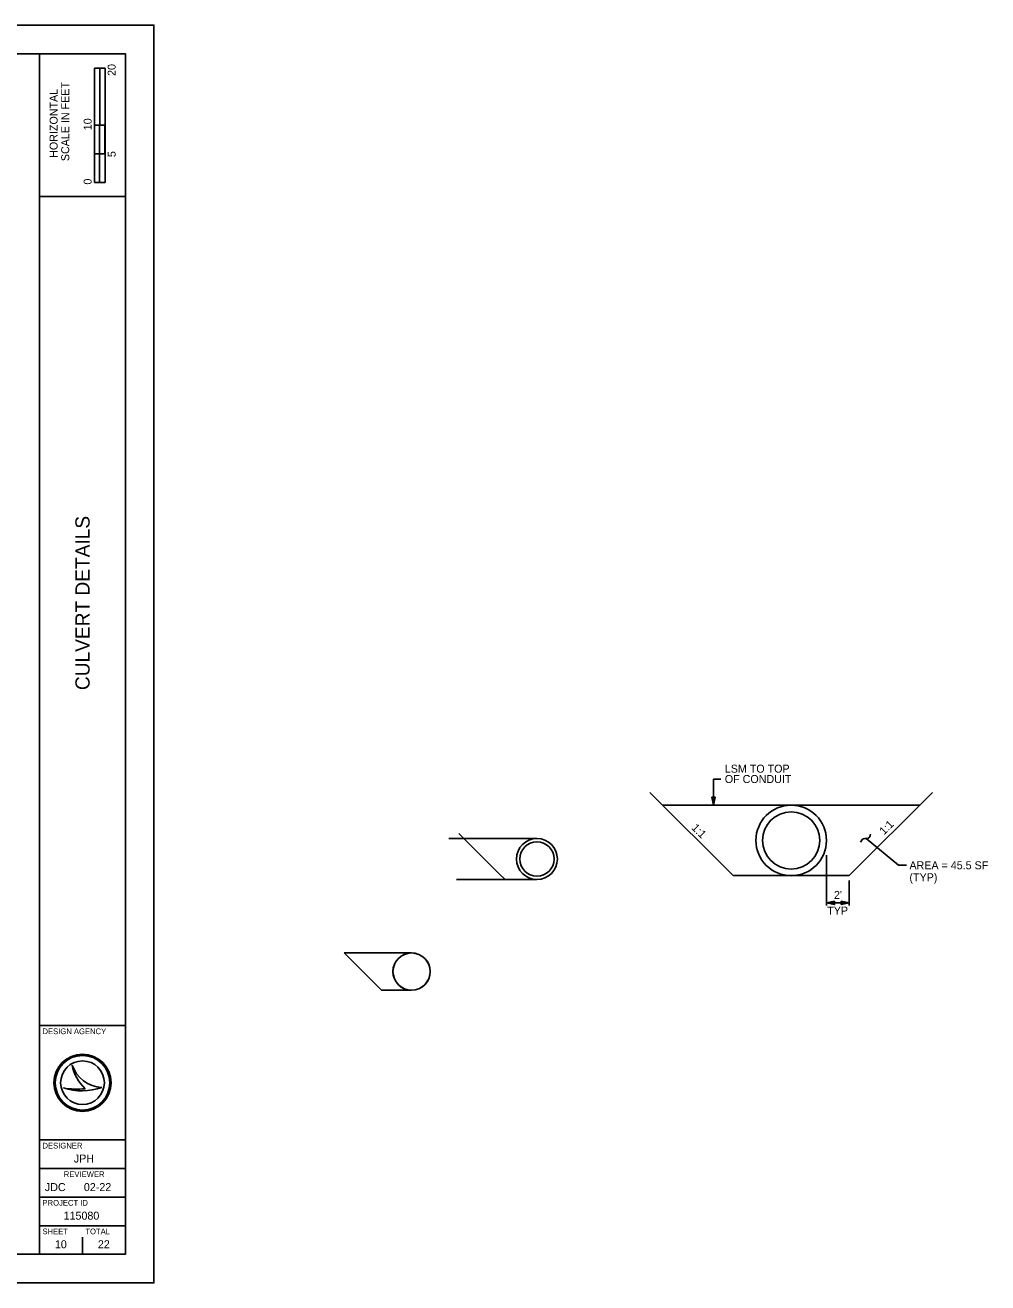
# Model space of a CAD drawing. Extents: x 0 to 486, y 0 to 220.
# Drawn here: x 317.5 to 485.8, y 0 to 220 of the extents above; entities that cross this region are included whole.
import ezdxf

# ---------------------------------------------------------------- set-up
doc = ezdxf.new("R2010")
doc.units = 0
for name, color, linetype in [('DR_P_Culvert', 7, 'Continuous'), ('DR_X_Culvert', 7, 'Continuous'), ('GE_X_Alignment', 7, 'Continuous'), ('GE_X_Alignment_100_Cardinal_Points', 7, 'Continuous'), ('MT_P_Temp_Road', 7, 'Continuous'), ('PF_X_Ground_Line', 7, 'Continuous'), ('XS_X_Pavt', 7, 'Continuous')]:
    doc.layers.add(name, color=color, linetype=linetype)

msp = doc.modelspace()

# ---------------------------------------------------------------- linework, layer by layer
at = {"layer": 'DR_P_Culvert'}
for p, q in [((406.97, 77.73), (391.55, 77.73)), ((406.97, 70.56), (392.92, 70.56)), ((385.05, 57.72), (373.26, 57.72)), ((379.79, 51.19), (373.26, 57.72)), ((385.05, 51.19), (379.79, 51.19))]:
    msp.add_line(p, q, dxfattribs=at)
msp.add_lwpolyline([(401.39, 70.56), (400.39, 71.56), (393.34, 78.61)], dxfattribs=at)
for centre, radius in [((406.97, 74.14), 3.58), ((406.97, 74.14), 3), ((385.05, 54.45), 3.26), ((385.05, 54.45), 3.25)]:
    msp.add_circle(centre, radius, dxfattribs=at)
at = {"layer": 'DR_X_Culvert'}
msp.add_lwpolyline([(0, 0), (340, 0), (340, 220), (0, 220)], close=True, dxfattribs=at)
at = {"layer": 'GE_X_Alignment'}
for points in [[(437.56, 84.96), (438.12, 84.96), (437.84, 83.56)], [(459, 66.74), (459, 66.18), (457.6, 66.46)], [(460.2, 66.18), (460.2, 66.74), (461.6, 66.46)]]:
    msp.add_lwpolyline(points, close=True, dxfattribs=at)
at = {"layer": 'GE_X_Alignment_100_Cardinal_Points'}
for p, q in [((437.84, 83.56), (437.84, 88.13)), ((437.84, 88.13), (439.14, 88.13)), ((464.54, 77.71), (470.21, 73.04)), ((457.6, 74.8), (457.6, 66.02)), ((470.21, 73.04), (471.58, 73.04)), ((461.6, 70.4), (461.6, 66.02)), ((457.6, 66.46), (461.6, 66.46))]:
    msp.add_line(p, q, dxfattribs=at)
msp.add_spline([(463.58, 77.07), (464.09, 77.68), (464.96, 77.77), (465.33, 78.5)], degree=3, dxfattribs=at)
at = {"layer": 'MT_P_Temp_Road'}
for p, q in [((441.27, 71.23), (426.72, 85.78)), ((461.6, 71.23), (476.16, 85.78)), ((473.94, 83.56), (428.94, 83.56)), ((441.27, 71.23), (451.44, 71.23)), ((451.44, 71.23), (461.6, 71.23))]:
    msp.add_line(p, q, dxfattribs=at)
for radius in [6.17, 5]:
    msp.add_circle((451.44, 77.39), radius, dxfattribs=at)
at = {"layer": 'PF_X_Ground_Line'}
for p, q in [((320, 5), (320, 215)), ((320, 190), (335, 190)), ((320, 45), (335, 45)), ((320, 25), (335, 25)), ((320, 20), (335, 20)), ((320, 15), (335, 15)), ((320, 10), (335, 10))]:
    msp.add_line(p, q, dxfattribs=at)
msp.add_lwpolyline([(15, 215), (335, 215), (335, 5), (15, 5)], close=True, dxfattribs=at)
at = {"layer": 'XS_X_Pavt'}
for p, q in [((329.57, 192.5), (329.57, 212.5)), ((331.44, 212.5), (329.57, 212.5)), ((329.57, 202.5), (329.57, 212.5)), ((329.57, 212.5), (330.5, 212.5)), ((330.5, 212.5), (330.51, 212.5)), ((330.51, 212.5), (330.51, 202.5)), ((331.44, 212.5), (331.44, 192.5)), ((330.51, 202.5), (329.57, 202.5)), ((331.43, 202.5), (330.5, 202.5)), ((330.5, 202.5), (330.5, 197.5)), ((331.43, 197.5), (331.43, 202.5)), ((330.5, 197.5), (329.57, 197.5)), ((329.57, 197.5), (329.57, 192.5)), ((330.5, 192.5), (330.5, 197.5)), ((330.5, 197.5), (331.43, 197.5)), ((331.44, 192.5), (329.57, 192.5)), ((329.57, 192.5), (330.5, 192.5)), ((325.67, 38.1), (325.67, 38.1)), ((324.17, 34.1), (324.17, 34.1)), ((327.5, 35), (327.5, 35)), ((330.87, 34.19), (330.87, 34.19)), ((323.75, 6.75), (323.75, 6.75)), ((327.5, 5), (327.5, 8))]:
    msp.add_line(p, q, dxfattribs=at)
for radius in [5, 4.77, 4.77, 3.82]:
    msp.add_circle((327.5, 35), radius, dxfattribs=at)
for centre, radius, start, end in [((331.16, 39.98), 5.8, 198.9257, 198.9319), ((333.47, 39.7), 7.96, 191.6379, 191.6421), ((331.16, 39.98), 5.8, 198.9319, 267.1657), ((333.47, 39.7), 7.96, 191.6421, 226.0947), ((327.39, 43.7), 10.13, 251.4576, 290.0832), ((326.48, 46.54), 12.66, 259.4964, 259.4995), ((327.39, 43.7), 10.13, 251.4527, 251.4576), ((326.48, 46.54), 12.66, 259.4995, 276.6672)]:
    msp.add_arc(centre, radius, start, end, dxfattribs=at)

# ---------------------------------------------------------------- texts
at = {"layer": 'GE_X_Alignment_100_Cardinal_Points'}
for s, p in [('LSM TO TOP', (439.83, 89.24)), ('OF CONDUIT', (439.83, 87.43)), ('AREA = 45.5 SF', (472.12, 72.34)), ('(TYP)', (472.12, 70.24)), ("2'", (458.92, 67.16)), ('TYP', (457.74, 64.41))]:
    msp.add_text(s, height=1.4, dxfattribs=at).set_placement(p)
for rotation, p in [(315, (433.92, 79.49)), (45, (467.68, 78.25))]:
    msp.add_text('1:1', height=1.4, rotation=rotation, dxfattribs=at).set_placement(p)
at = {"layer": 'XS_X_Pavt'}
for s, height, p in [('20', 1.4, (333.3, 211.12)), ('SCALE IN FEET', 1.4, (325.18, 196.21)), ('HORIZONTAL', 1.4, (323.15, 196.79)), ('10', 1.4, (329.1, 201.62)), ('5', 1.4, (333.3, 196.91)), ('0', 1.4, (329.1, 192.11)), ('CULVERT DETAILS', 2.5, (328.75, 103.69))]:
    msp.add_text(s, height=height, rotation=90, dxfattribs=at).set_placement(p)
for s, height, p in [('DESIGN AGENCY', 1, (320.5, 43.5)), ('DESIGNER', 1, (320.5, 23.5)), ('JPH', 1.4, (325.98, 21.05)), ('REVIEWER', 1, (324.22, 18.5)), ('JDC', 1.4, (320.91, 16.05)), ('02-22', 1.4, (327.74, 16.05)), ('PROJECT ID', 1, (320.5, 13.5)), ('115080', 1.4, (324.19, 11.05)), ('SHEET', 1, (320.5, 8.5)), ('TOTAL', 1, (328, 8.5)), ('10', 1.4, (322.67, 6.05)), ('22', 1.4, (330.19, 6.05))]:
    msp.add_text(s, height=height, dxfattribs=at).set_placement(p)

doc.saveas('drawing.dxf')
